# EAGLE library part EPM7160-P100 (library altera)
EPM7160E MAX 7000 family
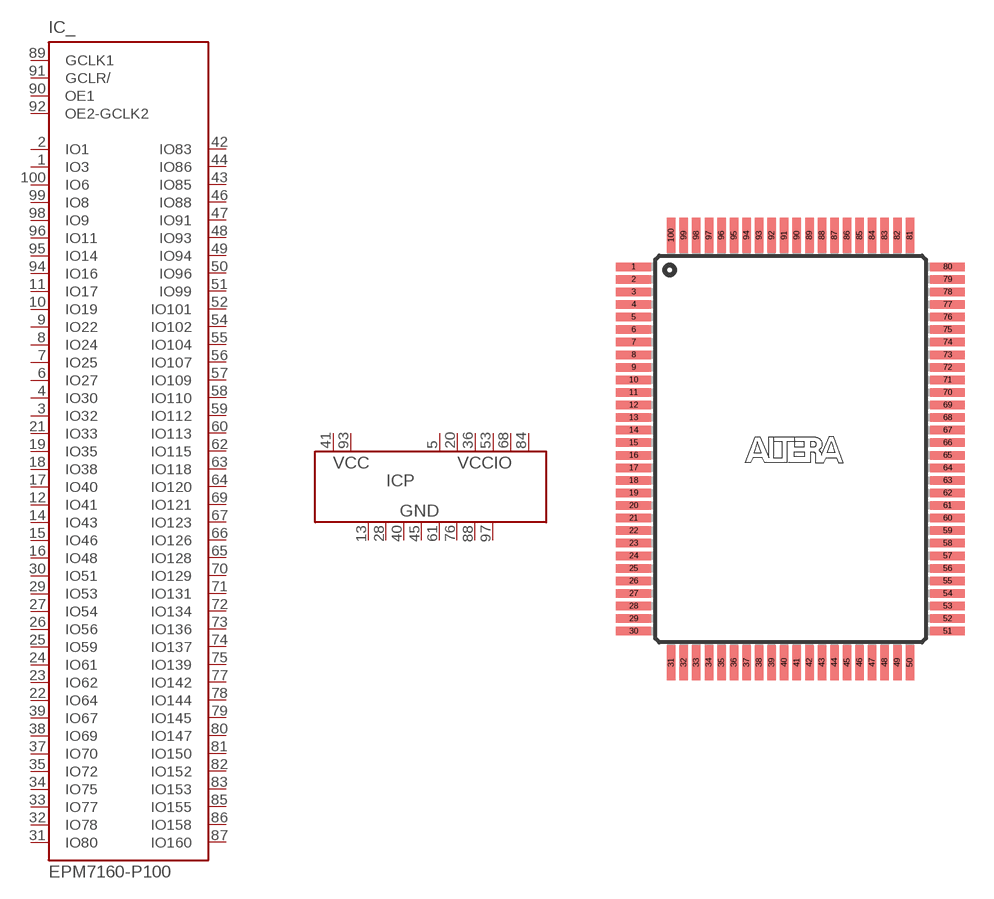
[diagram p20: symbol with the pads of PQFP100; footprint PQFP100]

Designator prefix IC; gates _=7160P100 P=PWR8-2-6

## EPM7160-P100  [PQFP100]
1  _:IO3
2  _:IO1
3  _:IO32
4  _:IO30
5  P:VCCIO  pwr
6  _:IO27
7  _:IO25
8  _:IO24
9  _:IO22
10  _:IO19
11  _:IO17
12  _:IO41
13  P:GND  pwr
14  _:IO43
15  _:IO46
16  _:IO48
17  _:IO40
18  _:IO38
19  _:IO35
20  P:VCCIO  pwr
21  _:IO33
22  _:IO64
23  _:IO62
24  _:IO61
25  _:IO59
26  _:IO56
27  _:IO54
28  P:GND  pwr
29  _:IO53
30  _:IO51
31  _:IO80
32  _:IO78
33  _:IO77
34  _:IO75
35  _:IO72
36  P:VCCIO  pwr
37  _:IO70
38  _:IO69
39  _:IO67
40  P:GND  pwr
41  P:VCC  pwr
42  _:IO83
43  _:IO85
44  _:IO86
45  P:GND  pwr
46  _:IO88
47  _:IO91
48  _:IO93
49  _:IO94
50  _:IO96
51  _:IO99
52  _:IO101
53  P:VCCIO  pwr
54  _:IO102
55  _:IO104
56  _:IO107
57  _:IO109
58  _:IO110
59  _:IO112
60  _:IO113
61  P:GND  pwr
62  _:IO115
63  _:IO118
64  _:IO120
65  _:IO128
66  _:IO126
67  _:IO123
68  P:VCCIO  pwr
69  _:IO121
70  _:IO129
71  _:IO131
72  _:IO134
73  _:IO136
74  _:IO137
75  _:IO139
76  P:GND  pwr
77  _:IO142
78  _:IO144
79  _:IO145
80  _:IO147
81  _:IO150
82  _:IO152
83  _:IO153
84  P:VCCIO  pwr
85  _:IO155
86  _:IO158
87  _:IO160
88  P:GND  pwr
89  _:GCLK1  in
90  _:OE1  in
91  _:GCLR/  in
92  _:OE2-GCLK2  in
93  P:VCC  pwr
94  _:IO16
95  _:IO14
96  _:IO11
97  P:GND  pwr
98  _:IO9
99  _:IO8
100  _:IO6

## Footprint PQFP100 (pad centres in mm)
Plastic Quad Flat Pack
smd 1.8 x 0.44: 1 -8.125,9.425; 2 -8.125,8.775; 3 -8.125,8.125; 4 -8.125,7.475; 5 -8.125,6.825; 6 -8.125,6.175; 7 -8.125,5.525; 8 -8.125,4.875; 9 -8.125,4.225; 10 -8.125,3.575; 11 -8.125,2.925; 12 -8.125,2.275; 13 -8.125,1.625; 14 -8.125,0.975; 15 -8.125,0.325; 16 -8.125,-0.325; 17 -8.125,-0.975; 18 -8.125,-1.625; 19 -8.125,-2.275; 20 -8.125,-2.925; 21 -8.125,-3.575; 22 -8.125,-4.225; 23 -8.125,-4.875; 24 -8.125,-5.525; 25 -8.125,-6.175; 26 -8.125,-6.825; 27 -8.125,-7.475; 28 -8.125,-8.125; 29 -8.125,-8.775; 30 -8.125,-9.425; 51 8.125,-9.425; 52 8.125,-8.775; 53 8.125,-8.125; 54 8.125,-7.475; 55 8.125,-6.825; 56 8.125,-6.175; 57 8.125,-5.525; 58 8.125,-4.875; 59 8.125,-4.225; 60 8.125,-3.575; 61 8.125,-2.925; 62 8.125,-2.275; 63 8.125,-1.625; 64 8.125,-0.975; 65 8.125,-0.325; 66 8.125,0.325; 67 8.125,0.975; 68 8.125,1.625; 69 8.125,2.275; 70 8.125,2.925; 71 8.125,3.575; 72 8.125,4.225; 73 8.125,4.875; 74 8.125,5.525; 75 8.125,6.175; 76 8.125,6.825; 77 8.125,7.475; 78 8.125,8.125; 79 8.125,8.775; 80 8.125,9.425
smd 0.44 x 1.8: 31 -6.175,-11.05; 32 -5.525,-11.05; 33 -4.875,-11.05; 34 -4.225,-11.05; 35 -3.575,-11.05; 36 -2.925,-11.05; 37 -2.275,-11.05; 38 -1.625,-11.05; 39 -0.975,-11.05; 40 -0.325,-11.05; 41 0.325,-11.05; 42 0.975,-11.05; 43 1.625,-11.05; 44 2.275,-11.05; 45 2.925,-11.05; 46 3.575,-11.05; 47 4.225,-11.05; 48 4.875,-11.05; 49 5.525,-11.05; 50 6.175,-11.05; 81 6.175,11.05; 82 5.525,11.05; 83 4.875,11.05; 84 4.225,11.05; 85 3.575,11.05; 86 2.925,11.05; 87 2.275,11.05; 88 1.625,11.05; 89 0.975,11.05; 90 0.325,11.05; 91 -0.325,11.05; 92 -0.975,11.05; 93 -1.625,11.05; 94 -2.275,11.05; 95 -2.925,11.05; 96 -3.575,11.05; 97 -4.225,11.05; 98 -4.875,11.05; 99 -5.525,11.05; 100 -6.175,11.05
